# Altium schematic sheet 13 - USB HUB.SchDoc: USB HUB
size A3; PageSetup: Record=PageOptions¦CenterHorizontal=True¦CenterVertical=True¦PrintScale=0.70¦XCorrection=1.00¦YCorrection=1.00¦PrintKind=0¦BorderSize=5000000¦LeftOffset=0¦BottomOffset=0¦Orientation=2¦PaperLength=4200¦PaperWidth=2970¦Scale=100¦PaperSource=7¦PrintQuality=600¦MediaType=1¦DitherType=10¦PaperKind=A4¦PrintScaleMode=1; Author: Juan Anzola; SheetNumber: 13; SheetTotal: 20
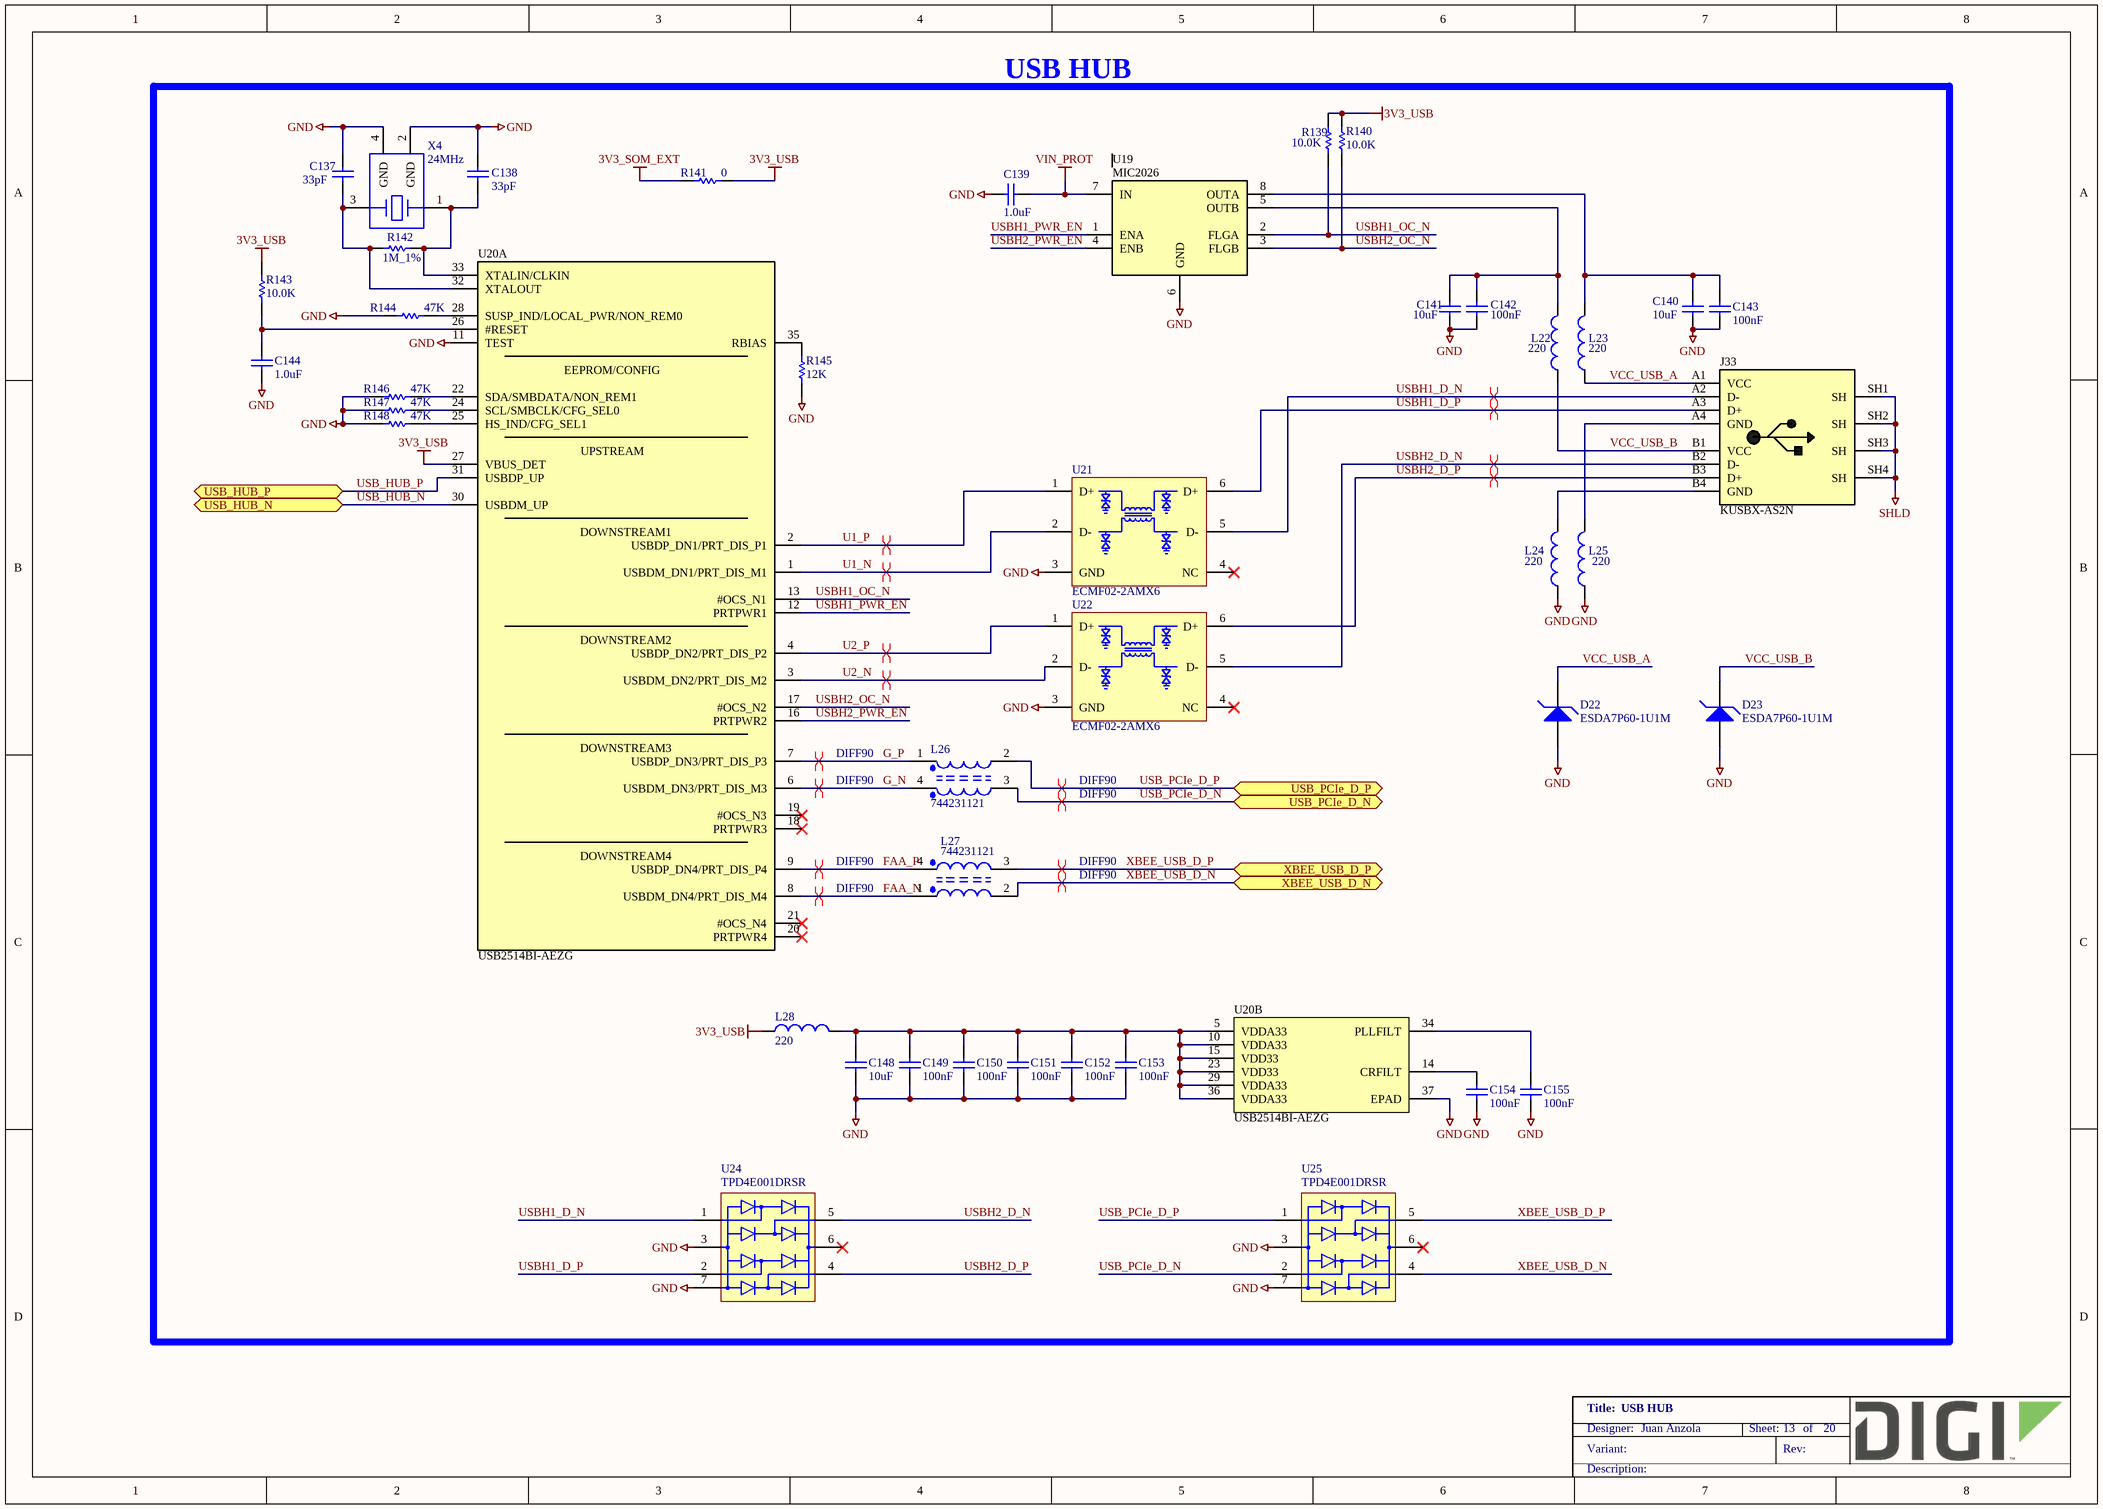
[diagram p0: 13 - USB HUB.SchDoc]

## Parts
C137  33pF  [CAPC1005X55N]
C138  33pF  [CAPC1005X55N]
C139  1.0uF  [CAPC1005X55N]
C140  10uF  [CAPC1005X55N]
C141  10uF  [CAPC1005X55N]
C142  100nF  [CAPC1005X55N]
C143  100nF  [CAPC1005X55N]
C144  1.0uF  [CAPC1005X55N]
C148  10uF  [CAPC1005X55N]
C149  100nF  [CAPC1005X55N]
C150  100nF  [CAPC1005X55N]
C151  100nF  [CAPC1005X55N]
C152  100nF  [CAPC1005X55N]
C153  100nF  [CAPC1005X55N]
C154  100nF  [CAPC1005X55N]
C155  100nF  [CAPC1005X55N]
D22  ESDA7P60-1U1M  [IND_1610]
D23  ESDA7P60-1U1M  [IND_1610]
J33  KUSBX-AS2N  [KYCON_KUSBX-AS2N_Flex]
L22  220  [INDC2013X110N]
L23  220  [INDC2013X110N]
L24  220  [INDC2013X110N]
L25  220  [INDC2013X110N]
L26  744231121  [FIL_DLW21H]
L27  744231121  [FIL_DLW21H]
L28  220  [INDC2013X110N]
R139  10.0K  [RESC1005X40N]
R140  10.0K  [RESC1005X40N]
R141  0  [RESC1609X55N]
R142  1M_1%  [RESC1005X40N]
R143  10.0K  [RESC1005X40N]
R144  47K  [RESC1005X40N]
R145  12K  [RESC1609X55N]
R146  47K  [RESC1005X40N]
R147  47K  [RESC1005X40N]
R148  47K  [RESC1005X40N]
U19  MIC2026  [SOIC127P600X175-8N]
U20  USB2514BI-AEZG  [QFN50P600X600X100-37AN]  (parts A,B of 2)
U21  ECMF02-2AMX6  [QFN_6L_1.7mmX1.5mm_STM]
U22  ECMF02-2AMX6  [QFN_6L_1.7mmX1.5mm_STM]
U24  TPD4E001DRSR  [SON95P300X300X80-7N]
U25  TPD4E001DRSR  [SON95P300X300X80-7N]
X4  24MHz  [XTAL_C3E-3427]

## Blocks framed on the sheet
USB HUB: C137-C144 C148-C155 D22 D23 J33 L22-L28 R139-R148 U19-U22 U24 U25 X4

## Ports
USB_HUB_N (bidir), USB_HUB_P (bidir), USB_PCIe_D_N (bidir), USB_PCIe_D_P (bidir), XBEE_USB_D_N (bidir), XBEE_USB_D_P (bidir)

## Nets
3V3_SOM_EXT: R141.1
3V3_USB: L28.2 R139.2 R140.2 R141.2 R143.2 U20.27(VBUS_DET)
GND: C137.2 C138.2 C139.2 C140.1 C141.1 C142.1 C143.1 C144.1 C148.1 C149.1 C150.1 C151.1 C152.1 C153.1 C154.1 C155.1 D22.A D23.A L24.1 L25.1 R144.2 R145.1 R146.1 R147.1 R148.1 U19.6(GND) U20.11(TEST) U20.37(EPAD) U21.3(GND) U22.3(GND) U24.3(GND) U24.7(GND) U25.3(GND) U25.7(GND) X4.2(GND) X4.4(GND)
SHLD: J33.SH1(SH) J33.SH2(SH) J33.SH3(SH) J33.SH4(SH)
VIN_PROT: C139.1 U19.7(IN)
FAA_N: L27.1 U20.8(USBDM_DN4/PRT_DIS_M4)
FAA_P: L27.4 U20.9(USBDP_DN4/PRT_DIS_P4)
G_N: L26.4 U20.6(USBDM_DN3/PRT_DIS_M3)
G_P: L26.1 U20.7(USBDP_DN3/PRT_DIS_P3)
U1_N: U20.1(USBDM_DN1/PRT_DIS_M1) U21.2(D-)
U1_P: U20.2(USBDP_DN1/PRT_DIS_P1) U21.1(D+)
U2_N: U20.3(USBDM_DN2/PRT_DIS_M2) U22.2(D-)
U2_P: U20.4(USBDP_DN2/PRT_DIS_P2) U22.1(D+)
USB_HUB_N: U20.30(USBDM_UP) ; port USB_HUB_N
USB_HUB_P: U20.31(USBDP_UP) ; port USB_HUB_P
USB_PCIe_D_N: L26.3 U25.2(I/O) ; port USB_PCIe_D_N
USB_PCIe_D_P: L26.2 U25.1(I/O) ; port USB_PCIe_D_P
USBH1_D_N: J33.A2(D-) U21.5(D-) U24.1(I/O)
USBH1_D_P: J33.A3(D+) U21.6(D+) U24.2(I/O)
USBH1_OC_N: R139.1 U19.2(FLGA) U20.13(#OCS_N1)
USBH1_PWR_EN: U19.1(ENA) U20.12(PRTPWR1)
USBH2_D_N: J33.B2(D-) U22.5(D-) U24.5(I/O)
USBH2_D_P: J33.B3(D+) U22.6(D+) U24.4(I/O)
USBH2_OC_N: R140.1 U19.3(FLGB) U20.17(#OCS_N2)
USBH2_PWR_EN: U19.4(ENB) U20.16(PRTPWR2)
VCC_USB_A: D22.K J33.A1(VCC) L23.1
VCC_USB_B: D23.K J33.B1(VCC) L22.1
XBEE_USB_D_N: L27.2 U25.4(I/O) ; port XBEE_USB_D_N
XBEE_USB_D_P: L27.3 U25.5(I/O) ; port XBEE_USB_D_P
NetC137_1: C137.1 R142.1 U20.32(XTALOUT) X4.3
NetC138_1: C138.1 R142.2 U20.33(XTALIN/CLKIN) X4.1
NetC140_2: C140.2 C143.2 L23.2 U19.8(OUTA)
NetC141_2: C141.2 C142.2 L22.2 U19.5(OUTB)
NetC144_2: C144.2 R143.1 U20.26(#RESET)
NetC148_2: C148.2 C149.2 C150.2 C151.2 C152.2 C153.2 L28.1 U20.5(VDDA33) U20.10(VDDA33) U20.15(VDD33) U20.23(VDD33) U20.29(VDDA33) U20.36(VDDA33)
NetC154_2: C154.2 U20.14(CRFILT)
NetC155_2: C155.2 U20.34(PLLFILT)
NetJ33_A4: J33.A4(GND) L25.2
NetJ33_B4: J33.B4(GND) L24.2
NetR144_1: R144.1 U20.28(SUSP_IND/LOCAL_PWR/NON_REM0)
NetR145_2: R145.2 U20.35(RBIAS)
NetR146_2: R146.2 U20.22(SDA/SMBDATA/NON_REM1)
NetR147_2: R147.2 U20.24(SCL/SMBCLK/CFG_SEL0)
NetR148_2: R148.2 U20.25(HS_IND/CFG_SEL1)

Not connected (* = marked no-connect by the designer): U20 18(PRTPWR3)* 19(#OCS_N3)* 20(PRTPWR4)* 21(#OCS_N4)*; U21 4(NC)*; U22 4(NC)*; U24 6(VCC)*; U25 6(VCC)*

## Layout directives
differential pair; differential pair class DIFF90: U1_N, U1_P, U2_N, U2_P, USBH1_D_N, USBH1_D_P, USBH2_D_N, USBH2_D_P
differential pair; net class DIFF90; differential pair class DIFF90: FAA_N, FAA_P, G_N, G_P, USB_PCIe_D_N, USB_PCIe_D_P, XBEE_USB_D_N, XBEE_USB_D_P

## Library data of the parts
C137 C138 = 1002646: CAP CER 33PF 50V C0G/NP0 0402; Part_Type: Capacitor; Manufacturer: Murata; Manufacturer_Part_Number: GCM1555C1H330JA16D; Digi_PN: 14050400; Component_Life_Cycle_State: Reviewed; Area: 2,12; Voltage: 50; Tolerance: 5%
C139 C144 = 1001167: CAP CER 1UF 10V 10% X5R 0402; Part_Type: Capacitor; Manufacturer: Murata; Manufacturer_Part_Number: GRM155R61A105KE15D; Digi_PN: 14050399; Component_Life_Cycle_State: Reviewed; Area: 0.95; Project: CCWMX6_SBC board
C140 C141 C148 = 1001168: CAP CER 10UF 10V 20% X5R 0402; Part_Type: Capacitor; Manufacturer: Samsung; Manufacturer_Part_Number: CL05A106MP5NUNC; Digi_PN: 14050689; Component_Life_Cycle_State: Reviewed; Area: 0.95; Project: CCWMX6_SBC board
C142 C143 C149-C155 = 1000006: CAP 100nF 16V 10% X7R 0402; Part_Type: Capacitor; Manufacturer: Murata; Manufacturer_Part_Number: GRM155R71C104KA88D; Component_Life_Cycle_State: CAD Reviewed; Area: 0.95; Project: KITT; Tolerance: 10; Digi_PN: 14050552
D22 D23 = 1002861: TVS DIODE 5VWM 11.6VC 1610; Part_Type: Diodes; Manufacturer: STMicroelectronics; Digi_PN: 17000341; Component_Life_Cycle_State: Pending
J33 = 1001121: USB Stacked Dual A type; Part_Type: Connector; Manufacturer: KYCON; Digi_PN: 18000276; Component_Life_Cycle_State: Reviewed; Area: 164; Project: CCWMX6_SBC board
L22-L25 L28 = 1001174: FERRITE BEAD 220 OHM 2.0A 0805; Manufacturer: Wurth Electronics Inc; Manufacturer_Part_Number: 742792022; Digi_PN: 21000146; Component_Life_Cycle_State: Reviewed; Area: 4.24; Project: CCWMX6_SBC board
L26 L27 = 1001173: CHOKE COM MODE 120 OHM .37A; Part_Type: Inductor; Manufacturer: Wurth Electronics Inc; Digi_PN: 21000143; Component_Life_Cycle_State: Reviewed; Area: 2.4; Project: CCWMX6_SBC board
R139 R140 R143 = 1000537: RES 10.0K OHM 1/10W 1% 0402 SMD; Part_Type: Resistor; Manufacturer: Panasonic - ECG; Manufacturer_Part_Number: ERJ-2RKF1002X; Component_Life_Cycle_State: CAD Reviewed; Area: 0.95; Project: KITT; Power_WV_SRF: 100; Digi_PN: 13051084
R141 = 1000208: RES 0.0 OHM 1/10W 0603; Part_Type: Resistor; Manufacturer: Panasonic - ECG; Manufacturer_Part_Number: ERJ-3GEY0R00V; Note: 13051103 = Digi No. for GE WDNU; Digi_PN: 13050568; Component_Life_Cycle_State: Reviewed; Area: 2.5; Project: Adjustable Foundation; Voltage: 75V
R142 = 1000971: RES 1.00M OHM 1/16W 1% 0402 SMD; Part_Type: Resistor; Manufacturer: Yageo; Manufacturer_Part_Number: RC0402FR-071ML; Digi_PN: 13050561; Component_Life_Cycle_State: Reviewed; Area: 0.95; Project: ConnectCore i.MX6 module; Power_WV_SRF: 63; Tolerance: 1; Note: 13051098 = Digi No. for GE WDNU
R144 R146-R148 = 1001155: RES 47.0K OHM 1/16W 1% 0402 SMD; Part_Type: Resistor; Manufacturer: Vishay Dale; Manufacturer_Part_Number: CRCW040247K0FKED; Digi_PN: 13050646; Component_Life_Cycle_State: Reviewed; Area: 0.95; Project: CCWMX6_SBC board
R145 = 1001200: RES 12.0K OHM 1/10W 1% 0603 SMD; Part_Type: Resistor; Manufacturer: Yageo; Manufacturer_Part_Number: RC0603FR-0712KL; Digi_PN: 13050531; Component_Life_Cycle_State: Reviewed; Area: 2.5; Project: LuCoV2; Power_WV_SRF: 100; Tolerance: 1
U19 = 1001143: IC SW DISTRIBUTION 2CHAN 8SOIC; Manufacturer: Micrel; Manufacturer_Part_Number: MIC2026-1YM; Digi_PN: 16051879; Component_Life_Cycle_State: Reviewed; Area: 29.58; Project: CCWMX6_SBC board
U20 = 1001114: 4-PORT USB 2.0 HUB CTRLR 36VQFN; Part_Type: IC; Manufacturer: SMSC; Digi_PN: 16051280; Component_Life_Cycle_State: Reviewed; Area: 36; Project: CCWMX6_SBC board
U21 U22 = 1002838: SMIC, COMMON MODE USB2.0/MIPI + ESD, QFN6, -40/+125°C
U24 U25 = 1001265: TVS DIODE 5.5VWM 6SON; Part_Type: IC; Manufacturer: Texas Instruments; Digi_PN: 17050690; Component_Life_Cycle_State: Reviewed; Area: 10; Project: CCWMX6_SBC board; Note: 17050839 = Digi No. for GE WDNU
X4 = 1001134: CRYSTAL 24MHZ 18PF SMD; Part_Type: Crystals-Oscillators; Manufacturer: Aker; Manufacturer_Part_Number: C3E-24.000-18-3030-X-R; Digi_PN: 20000223; Component_Life_Cycle_State: Reviewed; Area: 9.18; Project: CCWMX6_SBC board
